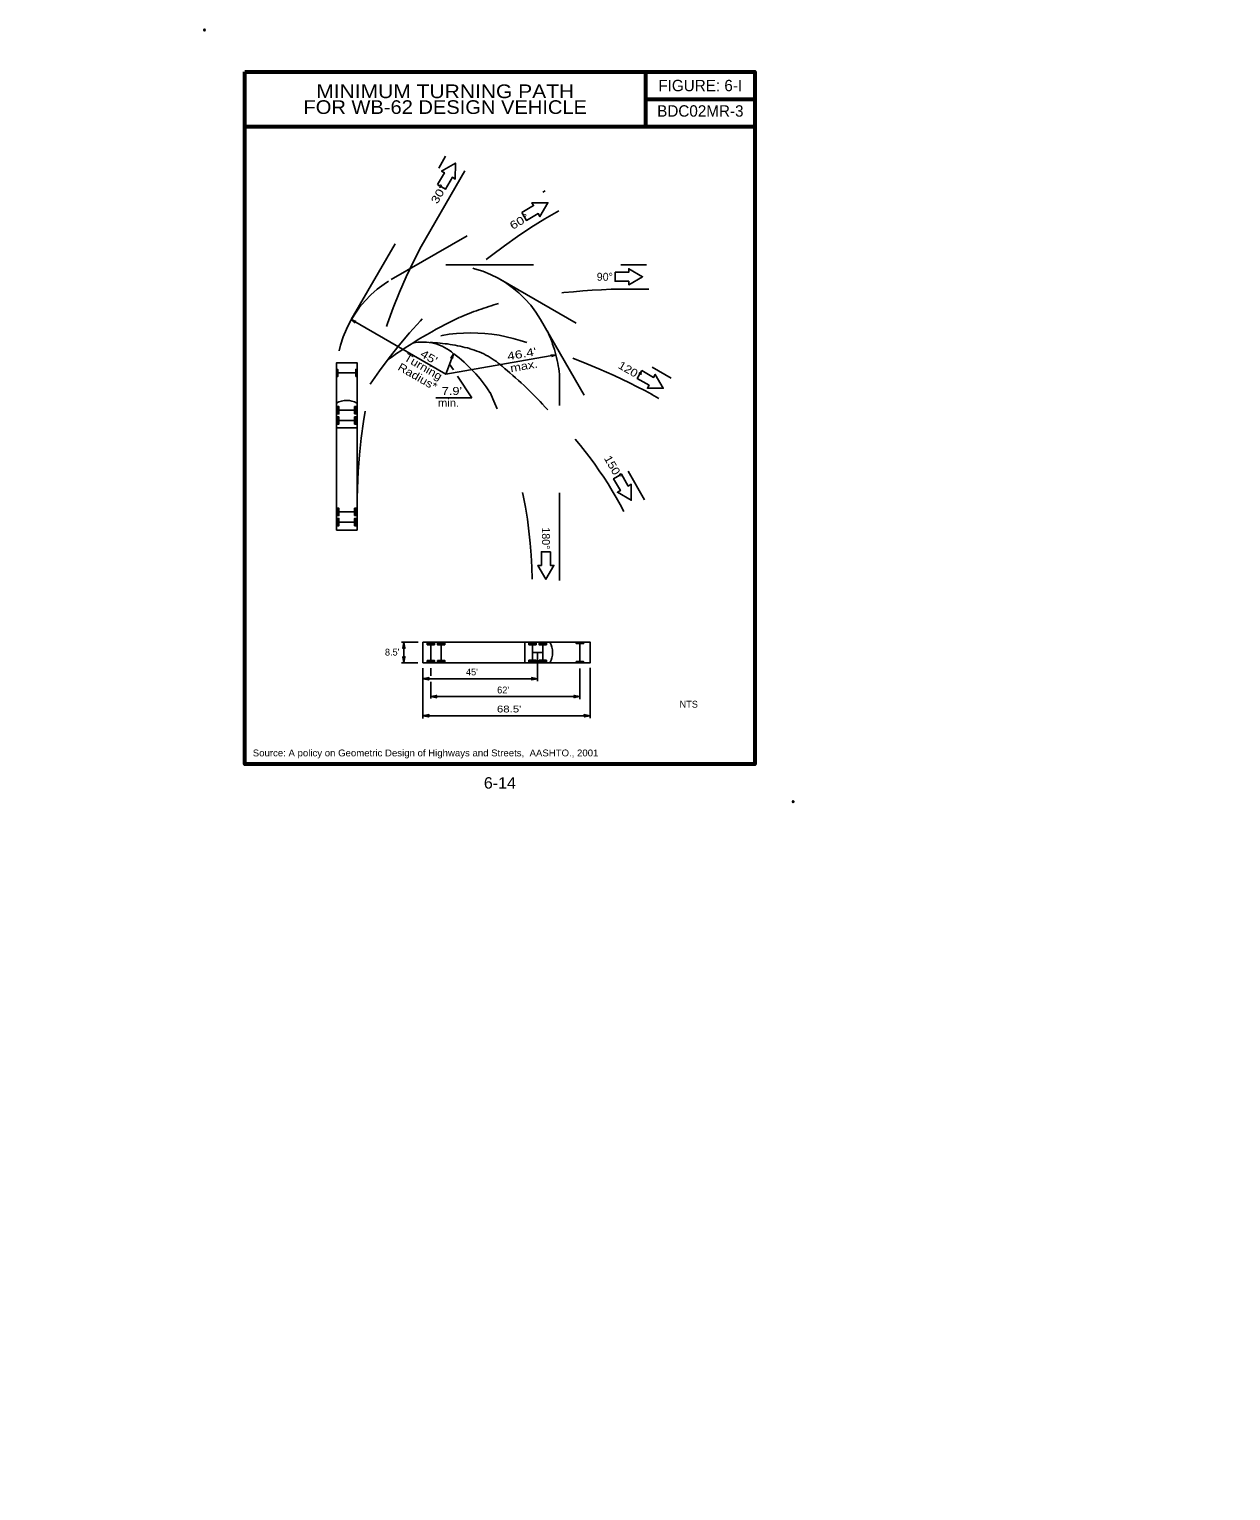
# Model space of a CAD drawing. Extents: x -5.68 to -4.31, y 4.1 to 5.77.
import ezdxf
from ezdxf.enums import TextEntityAlignment as Align

# ---------------------------------------------------------------- set-up
doc = ezdxf.new("R2010")
doc.units = 0
doc.header["$LTSCALE"] = 0.0036
doc.header["$PDMODE"] = 32
doc.header["$PDSIZE"] = 0.0018
doc.linetypes.add('LONG_DASHED', pattern=[7.5, 6, -1.5])
for name, color, linetype, lineweight in [('1', 7, 'Continuous', 25), ('2', 7, 'Continuous', 25), ('24', 7, 'Continuous', 25)]:
    doc.layers.add(name, color=color, linetype=linetype, lineweight=lineweight)

msp = doc.modelspace()

# ---------------------------------------------------------------- linework, layer by layer
at = {"layer": '1', "lineweight": 53}
for p, q in [((-4.977792, 5.724317), (-4.977792, 5.661817)), ((-4.977792, 5.693067), (-4.852792, 5.693067)), ((-5.436125, 5.661817), (-4.852792, 5.661817))]:
    msp.add_line(p, q, dxfattribs=at)
at = {"layer": '1', "linetype": 'LONG_DASHED'}
for p, q in [((-5.314383, 5.441033), (-5.206508, 5.627867)), ((-5.234508, 5.524675), (-5.182825, 5.614192)), ((-5.268633, 5.486783), (-5.092625, 5.5884)), ((-5.206133, 5.503533), (-4.976933, 5.503533)), ((-5.143633, 5.486783), (-4.948617, 5.374175)), ((-5.097883, 5.441033), (-4.978933, 5.235017)), ((-4.97085, 5.355442), (-4.962467, 5.3506))]:
    msp.add_line(p, q, dxfattribs=at)
at = {"layer": '1'}
for p, q in [((-5.314383, 5.441033), (-5.309375, 5.438975)), ((-5.197675, 5.401775), (-5.198808, 5.396483)), ((-5.080467, 5.400692), (-5.08555, 5.398842)), ((-5.329917, 5.37995), (-5.309267, 5.37995)), ((-5.328558, 5.337358), (-5.310708, 5.337358)), ((-5.307892, 5.31705), (-5.331267, 5.31705)), ((-5.328558, 5.325642), (-5.310708, 5.325642)), ((-5.328517, 5.2211), (-5.310667, 5.2211)), ((-5.328517, 5.209383), (-5.310667, 5.209383)), ((-5.237942, 5.071975), (-5.257067, 5.071975)), ((-5.254225, 5.048525), (-5.254225, 5.071933)), ((-5.223442, 5.069183), (-5.223442, 5.051333)), ((-5.211725, 5.069183), (-5.211725, 5.051333)), ((-5.115775, 5.048558), (-5.115775, 5.071933)), ((-5.107183, 5.069225), (-5.107183, 5.051375)), ((-5.095467, 5.069225), (-5.095467, 5.051375)), ((-5.052875, 5.070583), (-5.052875, 5.049933)), ((-5.238183, 5.048533), (-5.257067, 5.048533)), ((-5.107183, 5.0603), (-5.095467, 5.0603)), ((-5.101325, 5.0603), (-5.101325, 5.0432)), ((-5.232558, 5.042483), (-5.232558, 4.984942)), ((-5.223558, 5.042483), (-5.223558, 5.033517)), ((-5.101325, 5.0432), (-5.101325, 5.027375)), ((-5.052875, 5.042), (-5.052875, 5.006983)), ((-5.04115, 5.042608), (-5.04115, 4.985033)), ((-5.2325, 5.030367), (-5.101325, 5.030367)), ((-5.223558, 5.026792), (-5.223558, 5.007583)), ((-5.223558, 5.009867), (-5.052875, 5.009867)), ((-5.23255, 4.988033), (-5.04115, 4.988033))]:
    msp.add_line(p, q, dxfattribs=at)
at = {"layer": '1', "lineweight": 53}
msp.add_lwpolyline([(-5.436125, 5.724317), (-4.852792, 5.724317), (-4.852792, 4.93265), (-5.436125, 4.93265)], close=True, dxfattribs=at)
at = {"layer": '1'}
for points in [[(-5.215633, 5.595392), (-5.206617, 5.590183), (-5.1988, 5.603717), (-5.195425, 5.601758), (-5.195417, 5.619992), (-5.211217, 5.610883), (-5.207825, 5.608925)], [(-5.11935, 5.563508), (-5.114142, 5.554483), (-5.100617, 5.5623), (-5.098667, 5.558908), (-5.089542, 5.5747), (-5.107783, 5.5747), (-5.105825, 5.571317)], [(-5.012617, 5.495192), (-5.012617, 5.484775), (-4.996992, 5.484775), (-4.996992, 5.480867), (-4.9812, 5.489983), (-4.996992, 5.4991), (-4.996992, 5.495192)], [(-5.331308, 5.200267), (-5.331308, 5.391675), (-5.307875, 5.391675), (-5.307875, 5.200267)], [(-5.331308, 5.375783), (-5.331308, 5.384117), (-5.329917, 5.384117), (-5.329917, 5.375783)], [(-5.309267, 5.375783), (-5.309267, 5.384117), (-5.307875, 5.384117), (-5.307875, 5.375783)], [(-4.982158, 5.382725), (-4.987367, 5.3737), (-4.973833, 5.365892), (-4.975792, 5.362517), (-4.95755, 5.362508), (-4.966667, 5.378308), (-4.968625, 5.374908)], [(-5.33135, 5.333192), (-5.33135, 5.341525), (-5.329958, 5.341525), (-5.329958, 5.333192)], [(-5.329958, 5.333192), (-5.329958, 5.341525), (-5.328558, 5.341525), (-5.328558, 5.333192)], [(-5.310708, 5.333192), (-5.310708, 5.341525), (-5.309308, 5.341525), (-5.309308, 5.333192)], [(-5.309308, 5.333192), (-5.309308, 5.341525), (-5.307917, 5.341525), (-5.307917, 5.333192)], [(-5.33135, 5.321475), (-5.33135, 5.329808), (-5.329958, 5.329808), (-5.329958, 5.321475)], [(-5.329958, 5.321475), (-5.329958, 5.329808), (-5.328558, 5.329808), (-5.328558, 5.321475)], [(-5.310708, 5.321475), (-5.310708, 5.329808), (-5.309308, 5.329808), (-5.309308, 5.321475)], [(-5.309308, 5.321475), (-5.309308, 5.329808), (-5.307917, 5.329808), (-5.307917, 5.321475)], [(-5.005467, 5.2642), (-5.014492, 5.258992), (-5.006675, 5.245467), (-5.010058, 5.243517), (-4.994267, 5.234392), (-4.994267, 5.252633), (-4.997658, 5.250675)], [(-5.331308, 5.216933), (-5.331308, 5.225267), (-5.329917, 5.225267), (-5.329917, 5.216933)], [(-5.329917, 5.216933), (-5.329917, 5.225267), (-5.328517, 5.225267), (-5.328517, 5.216933)], [(-5.310667, 5.216933), (-5.310667, 5.225267), (-5.309267, 5.225267), (-5.309267, 5.216933)], [(-5.309267, 5.216933), (-5.309267, 5.225267), (-5.307875, 5.225267), (-5.307875, 5.216933)], [(-5.331308, 5.205217), (-5.331308, 5.21355), (-5.329917, 5.21355), (-5.329917, 5.205217)], [(-5.329917, 5.205217), (-5.329917, 5.21355), (-5.328517, 5.21355), (-5.328517, 5.205217)], [(-5.310667, 5.205217), (-5.310667, 5.21355), (-5.309267, 5.21355), (-5.309267, 5.205217)], [(-5.309267, 5.205217), (-5.309267, 5.21355), (-5.307875, 5.21355), (-5.307875, 5.205217)], [(-5.086575, 5.175575), (-5.096992, 5.175575), (-5.096992, 5.15995), (-5.100892, 5.15995), (-5.091783, 5.144158), (-5.082667, 5.15995), (-5.086575, 5.15995)], [(-5.232558, 5.071975), (-5.04115, 5.071975), (-5.04115, 5.048542), (-5.232558, 5.048542)], [(-5.227608, 5.071975), (-5.219275, 5.071975), (-5.219275, 5.070583), (-5.227608, 5.070583)], [(-5.227608, 5.070583), (-5.219275, 5.070583), (-5.219275, 5.069183), (-5.227608, 5.069183)], [(-5.215892, 5.071975), (-5.207558, 5.071975), (-5.207558, 5.070583), (-5.215892, 5.070583)], [(-5.215892, 5.070583), (-5.207558, 5.070583), (-5.207558, 5.069183), (-5.215892, 5.069183)], [(-5.11135, 5.072017), (-5.103017, 5.072017), (-5.103017, 5.070625), (-5.11135, 5.070625)], [(-5.11135, 5.070625), (-5.103017, 5.070625), (-5.103017, 5.069225), (-5.11135, 5.069225)], [(-5.099633, 5.072017), (-5.0913, 5.072017), (-5.0913, 5.070625), (-5.099633, 5.070625)], [(-5.099633, 5.070625), (-5.0913, 5.070625), (-5.0913, 5.069225), (-5.099633, 5.069225)], [(-5.057042, 5.071975), (-5.048708, 5.071975), (-5.048708, 5.070583), (-5.057042, 5.070583)], [(-5.227608, 5.051333), (-5.219275, 5.051333), (-5.219275, 5.049933), (-5.227608, 5.049933)], [(-5.227608, 5.049933), (-5.219275, 5.049933), (-5.219275, 5.048542), (-5.227608, 5.048542)], [(-5.215892, 5.051333), (-5.207558, 5.051333), (-5.207558, 5.049933), (-5.215892, 5.049933)], [(-5.215892, 5.049933), (-5.207558, 5.049933), (-5.207558, 5.048542), (-5.215892, 5.048542)], [(-5.11135, 5.051375), (-5.103017, 5.051375), (-5.103017, 5.049975), (-5.11135, 5.049975)], [(-5.11135, 5.049975), (-5.103017, 5.049975), (-5.103017, 5.048583), (-5.11135, 5.048583)], [(-5.099633, 5.051375), (-5.0913, 5.051375), (-5.0913, 5.049975), (-5.099633, 5.049975)], [(-5.099633, 5.049975), (-5.0913, 5.049975), (-5.0913, 5.048583), (-5.099633, 5.048583)], [(-5.057042, 5.049933), (-5.048708, 5.049933), (-5.048708, 5.048542), (-5.057042, 5.048542)]]:
    msp.add_lwpolyline(points, close=True, dxfattribs=at)
for points in [[(-5.310558, 5.438767), (-5.3101, 5.437492), (-5.314433, 5.441075)], [(-5.309383, 5.43895), (-5.31055, 5.438783), (-5.310558, 5.438767)], [(-5.199225, 5.397608), (-5.200392, 5.396933), (-5.197642, 5.401825)], [(-5.084825, 5.399775), (-5.086008, 5.400408), (-5.080408, 5.400692)], [(-5.085558, 5.39885), (-5.084808, 5.399758), (-5.084825, 5.399775)], [(-5.198833, 5.396483), (-5.199208, 5.3976), (-5.199225, 5.397608)]]:
    msp.add_lwpolyline(points, dxfattribs=at)
at = {"layer": '1', "linetype": 'LONG_DASHED'}
for centre, radius, start, end in [((-4.762043, 5.006607), 0.641577, 119.41729, 145.80266), ((-4.680067, 5.2306), 0.6276, 152.05893, 180.18091), ((-5.206134, 5.378533), 0.124999, 30.00165, 173.73609), ((-4.995637, 4.78883), 0.687172, 104.54706, 104.54706), ((-4.995637, 4.78883), 0.687172, 88.19199, 102.632), ((-5.02827, 5.055001), 0.42117, 106.21202, 112.69666), ((-4.940301, 4.927228), 0.573947, 115.91033, 125.34278), ((-5.177753, 5.2346), 0.191176, 70.39355, 109.69824), ((-5.240169, 5.359419), 0.16495, 6.65496, 24.52545), ((-5.232969, 5.361338), 0.054029, 48.88452, 101.79293), ((-5.23051, 5.225607), 0.189329, 74.18371, 88.12314), ((-5.301691, 5.263026), 0.173897, 32.98189, 53.0645), ((-5.204774, 5.315343), 0.09593, 47.34966, 74.27114), ((-5.328395, 4.69157), 0.754139, 61.6475, 73.45199), ((-5.41536, 5.047903), 0.43596, 41.67879, 50.76022), ((-5.643182, 5.135495), 0.535722, 0.92351, 24.49207), ((-5.420256, 4.999834), 0.472969, 27.97988, 45.5368)]:
    msp.add_arc(centre, radius, start, end, dxfattribs=at)
at = {"layer": '1'}
for centre, start, end in [((-5.319665, 5.325201), 60.0609, 119.9391), ((-5.107624, 5.060331), 330.0609, 29.9391)]:
    msp.add_arc(centre, 0.023418, start, end, dxfattribs=at)
for p in [(-5.482375, 5.772175), (-4.809042, 4.889675)]:
    msp.add_point(p, dxfattribs=at)
at = {"layer": '2'}
for p, q in [((-5.206133, 5.378533), (-5.314383, 5.441033)), ((-5.206133, 5.378533), (-5.197675, 5.401783)), ((-5.206133, 5.378533), (-5.080467, 5.400692)), ((-5.197442, 5.383375), (-5.201908, 5.390158)), ((-5.176483, 5.351583), (-5.192908, 5.376492)), ((-5.217567, 5.351583), (-5.176483, 5.351583))]:
    msp.add_line(p, q, dxfattribs=at)
at = {"layer": '2', "linetype": 'LONG_DASHED'}
msp.add_line((-5.076333, 5.142817), (-5.076333, 5.378533), dxfattribs=at)
at = {"layer": '24'}
for points in [[(-5.254225, 5.071933), (-5.25545, 5.065), (-5.254225, 5.066658), (-5.253017, 5.065042), (-5.254225, 5.071933), (-5.254217, 5.071475), (-5.255358, 5.0652), (-5.254208, 5.066792), (-5.253117, 5.065317), (-5.254192, 5.071225), (-5.254225, 5.070992), (-5.255183, 5.065617), (-5.254208, 5.066825), (-5.253267, 5.065583), (-5.254225, 5.070892), (-5.254192, 5.070658), (-5.255042, 5.065958), (-5.254225, 5.066875), (-5.253383, 5.065942), (-5.254192, 5.069992), (-5.254192, 5.0696), (-5.254867, 5.066308), (-5.254242, 5.06695), (-5.253558, 5.066258), (-5.254225, 5.069525), (-5.25425, 5.069158), (-5.254667, 5.066683), (-5.254192, 5.067158), (-5.253717, 5.066642), (-5.254225, 5.068817), (-5.254258, 5.068467), (-5.254542, 5.066983), (-5.254208, 5.067225), (-5.253842, 5.066825), (-5.254225, 5.068292), (-5.254458, 5.067317), (-5.254192, 5.067458), (-5.253925, 5.067033), (-5.254192, 5.068042), (-5.25435, 5.067408), (-5.254142, 5.067675), (-5.254017, 5.067367), (-5.254208, 5.067675), (-5.254242, 5.067517)], [(-5.254225, 5.048525), (-5.253, 5.055458), (-5.254225, 5.0538), (-5.255433, 5.055417), (-5.254225, 5.048525), (-5.254242, 5.048983), (-5.253092, 5.055258), (-5.254242, 5.053667), (-5.255333, 5.055142), (-5.254258, 5.049233), (-5.254225, 5.049467), (-5.253267, 5.054842), (-5.254242, 5.053633), (-5.255183, 5.054875), (-5.254225, 5.049567), (-5.254258, 5.0498), (-5.253408, 5.0545), (-5.254225, 5.053583), (-5.255067, 5.054517), (-5.254258, 5.050467), (-5.254258, 5.050858), (-5.253583, 5.05415), (-5.254208, 5.053508), (-5.254892, 5.0542), (-5.254225, 5.050933), (-5.2542, 5.0513), (-5.253783, 5.053775), (-5.254258, 5.0533), (-5.254733, 5.053817), (-5.254225, 5.051642), (-5.254192, 5.051992), (-5.253908, 5.053475), (-5.254242, 5.053233), (-5.254608, 5.053633), (-5.254225, 5.052167), (-5.253992, 5.053142), (-5.254258, 5.053), (-5.254525, 5.053425), (-5.254258, 5.052417), (-5.2541, 5.05305), (-5.254308, 5.052783), (-5.254433, 5.053092), (-5.254242, 5.052783), (-5.254208, 5.052942)], [(-5.2325, 5.030367), (-5.225567, 5.029142), (-5.227225, 5.030367), (-5.225608, 5.031575), (-5.2325, 5.030367), (-5.232042, 5.030383), (-5.225767, 5.029233), (-5.227358, 5.030383), (-5.225883, 5.031475), (-5.231792, 5.0304), (-5.231558, 5.030367), (-5.226183, 5.029408), (-5.227392, 5.030383), (-5.22615, 5.031325), (-5.231458, 5.030367), (-5.231225, 5.0304), (-5.226525, 5.02955), (-5.227442, 5.030367), (-5.226508, 5.031208), (-5.230558, 5.0304), (-5.230167, 5.0304), (-5.226875, 5.029725), (-5.227517, 5.03035), (-5.226825, 5.031033), (-5.230092, 5.030367), (-5.229725, 5.030342), (-5.22725, 5.029925), (-5.227725, 5.0304), (-5.227208, 5.030875), (-5.229383, 5.030367), (-5.229033, 5.030333), (-5.22755, 5.03005), (-5.227792, 5.030383), (-5.227392, 5.03075), (-5.228858, 5.030367), (-5.227883, 5.030133), (-5.228025, 5.0304), (-5.2276, 5.030667), (-5.228608, 5.0304), (-5.227975, 5.030242), (-5.228242, 5.03045), (-5.227933, 5.030575), (-5.228242, 5.030383), (-5.228083, 5.03035)], [(-5.101325, 5.030367), (-5.108258, 5.031592), (-5.1066, 5.030367), (-5.108217, 5.029158), (-5.101325, 5.030367), (-5.101783, 5.030358), (-5.108058, 5.0315), (-5.106467, 5.03035), (-5.107942, 5.029258), (-5.102033, 5.030333), (-5.102267, 5.030367), (-5.107642, 5.031325), (-5.106433, 5.03035), (-5.107675, 5.029408), (-5.102367, 5.030367), (-5.1026, 5.030333), (-5.1073, 5.031183), (-5.106383, 5.030367), (-5.107317, 5.029525), (-5.103267, 5.030333), (-5.103658, 5.030333), (-5.10695, 5.031008), (-5.106308, 5.030383), (-5.107, 5.0297), (-5.103733, 5.030367), (-5.1041, 5.030392), (-5.106575, 5.030808), (-5.1061, 5.030333), (-5.106617, 5.029858), (-5.104442, 5.030367), (-5.104792, 5.0304), (-5.106275, 5.030683), (-5.106033, 5.03035), (-5.106433, 5.029983), (-5.104967, 5.030367), (-5.105942, 5.0306), (-5.1058, 5.030333), (-5.106225, 5.030067), (-5.105217, 5.030333), (-5.10585, 5.030492), (-5.105583, 5.030283), (-5.105892, 5.030158), (-5.105583, 5.03035), (-5.105742, 5.030383)], [(-5.223558, 5.009867), (-5.216625, 5.008642), (-5.218283, 5.009867), (-5.216667, 5.011075), (-5.223558, 5.009867), (-5.2231, 5.009883), (-5.216825, 5.008733), (-5.218417, 5.009883), (-5.216942, 5.010975), (-5.22285, 5.0099), (-5.222617, 5.009867), (-5.217242, 5.008908), (-5.21845, 5.009883), (-5.217208, 5.010825), (-5.222517, 5.009867), (-5.222283, 5.0099), (-5.217583, 5.00905), (-5.2185, 5.009867), (-5.217567, 5.010708), (-5.221617, 5.0099), (-5.221225, 5.0099), (-5.217933, 5.009225), (-5.218575, 5.00985), (-5.217883, 5.010533), (-5.22115, 5.009867), (-5.220783, 5.009842), (-5.218308, 5.009425), (-5.218783, 5.0099), (-5.218267, 5.010375), (-5.220442, 5.009867), (-5.220092, 5.009833), (-5.218608, 5.00955), (-5.21885, 5.009883), (-5.21845, 5.01025), (-5.219917, 5.009867), (-5.218942, 5.009633), (-5.219083, 5.0099), (-5.218658, 5.010167), (-5.219667, 5.0099), (-5.219033, 5.009742), (-5.2193, 5.00995), (-5.218992, 5.010075), (-5.2193, 5.009883), (-5.219142, 5.00985)], [(-5.052875, 5.009867), (-5.059808, 5.011092), (-5.05815, 5.009867), (-5.059767, 5.008658), (-5.052875, 5.009867), (-5.053333, 5.009858), (-5.059608, 5.011), (-5.058017, 5.00985), (-5.059492, 5.008758), (-5.053583, 5.009833), (-5.053817, 5.009867), (-5.059192, 5.010825), (-5.057983, 5.00985), (-5.059225, 5.008908), (-5.053917, 5.009867), (-5.05415, 5.009833), (-5.05885, 5.010683), (-5.057933, 5.009867), (-5.058867, 5.009025), (-5.054817, 5.009833), (-5.055208, 5.009833), (-5.0585, 5.010508), (-5.057858, 5.009883), (-5.05855, 5.0092), (-5.055283, 5.009867), (-5.05565, 5.009892), (-5.058125, 5.010308), (-5.05765, 5.009833), (-5.058167, 5.009358), (-5.055992, 5.009867), (-5.056342, 5.0099), (-5.057825, 5.010183), (-5.057583, 5.00985), (-5.057983, 5.009483), (-5.056517, 5.009867), (-5.057492, 5.0101), (-5.05735, 5.009833), (-5.057775, 5.009567), (-5.056767, 5.009833), (-5.0574, 5.009992), (-5.057133, 5.009783), (-5.057442, 5.009658), (-5.057133, 5.00985), (-5.057292, 5.009883)], [(-5.23255, 4.988033), (-5.225617, 4.986808), (-5.227275, 4.988033), (-5.225658, 4.989242), (-5.23255, 4.988033), (-5.232092, 4.98805), (-5.225817, 4.9869), (-5.227408, 4.98805), (-5.225933, 4.989142), (-5.231842, 4.988067), (-5.231608, 4.988033), (-5.226233, 4.987075), (-5.227442, 4.98805), (-5.2262, 4.988992), (-5.231508, 4.988033), (-5.231275, 4.988067), (-5.226575, 4.987217), (-5.227492, 4.988033), (-5.226558, 4.988875), (-5.230608, 4.988067), (-5.230217, 4.988067), (-5.226925, 4.987392), (-5.227567, 4.988017), (-5.226875, 4.9887), (-5.230142, 4.988033), (-5.229775, 4.988008), (-5.2273, 4.987592), (-5.227775, 4.988067), (-5.227258, 4.988542), (-5.229433, 4.988033), (-5.229083, 4.988), (-5.2276, 4.987717), (-5.227842, 4.98805), (-5.227442, 4.988417), (-5.228908, 4.988033), (-5.227933, 4.9878), (-5.228075, 4.988067), (-5.22765, 4.988333), (-5.228658, 4.988067), (-5.228025, 4.987908), (-5.228292, 4.988117), (-5.227983, 4.988242), (-5.228292, 4.98805), (-5.228133, 4.988017)], [(-5.04115, 4.988033), (-5.048083, 4.989258), (-5.046425, 4.988033), (-5.048042, 4.986825), (-5.04115, 4.988033), (-5.041608, 4.988025), (-5.047883, 4.989167), (-5.046292, 4.988017), (-5.047767, 4.986925), (-5.041858, 4.988), (-5.042092, 4.988033), (-5.047467, 4.988992), (-5.046258, 4.988017), (-5.0475, 4.987075), (-5.042192, 4.988033), (-5.042425, 4.988), (-5.047125, 4.98885), (-5.046208, 4.988033), (-5.047142, 4.987192), (-5.043092, 4.988), (-5.043483, 4.988), (-5.046775, 4.988675), (-5.046133, 4.98805), (-5.046825, 4.987367), (-5.043558, 4.988033), (-5.043925, 4.988058), (-5.0464, 4.988475), (-5.045925, 4.988), (-5.046442, 4.987525), (-5.044267, 4.988033), (-5.044617, 4.988067), (-5.0461, 4.98835), (-5.045858, 4.988017), (-5.046258, 4.98765), (-5.044792, 4.988033), (-5.045767, 4.988267), (-5.045625, 4.988), (-5.04605, 4.987733), (-5.045042, 4.988), (-5.045675, 4.988158), (-5.045408, 4.98795), (-5.045717, 4.987825), (-5.045408, 4.988017), (-5.045567, 4.98805)]]:
    msp.add_lwpolyline(points, dxfattribs=at)

# ---------------------------------------------------------------- texts
at = {"layer": '1'}
for s, height, width, p in [('MINIMUM TURNING PATH', 0.01562, 1.15, (-5.206958, 5.694292)), ('FOR WB-62 DESIGN VEHICLE', 0.01562, 1.1, (-5.206958, 5.676217)), ('min.', 0.009117, 1.05, (-5.203229, 5.341258)), ("7.9'", 0.009117, 1.2, (-5.199454, 5.354817)), ('6-14', 0.01303, 1.05, (-5.144463, 4.90465))]:
    msp.add_text(s, height=height, dxfattribs=dict(at, width=width)).set_placement(p, align=Align.CENTER)
for s, height, p in [('FIGURE: 6-I', 0.01303, (-4.915292, 5.702175)), ('BDC02MR-3', 0.01303, (-4.915171, 5.6731)), ('NTS', 0.007817, (-4.928454, 4.997225))]:
    msp.add_text(s, height=height, dxfattribs=at).set_placement(p, align=Align.CENTER)
for s, rotation, width, p in [('30°', 60, 1.25, (-5.204546, 5.592462)), ('60°', 30, 1.25, (-5.109921, 5.555074)), ('120°', 330, 1.15, (-4.985096, 5.371639)), ('150°', 300, 1.15, (-5.011306, 5.257371))]:
    msp.add_text(s, height=0.009108, rotation=rotation, dxfattribs=dict(at, width=width)).set_placement(p, align=Align.RIGHT)
msp.add_text('90°', height=0.009108, dxfattribs=at).set_placement((-5.015225, 5.485425), align=Align.RIGHT)
for s, rotation, width, p in [('Turning', 329.999, 1.15, (-5.234321, 5.383065)), ("45'", 329.999, 1.25, (-5.227817, 5.394346)), ("46.4'", 9.999, 1.3, (-5.118629, 5.397299)), ('Radius*', 329.999, 1.15, (-5.240833, 5.371788)), ('max.', 9.999, 1.2, (-5.116191, 5.383497))]:
    msp.add_text(s, height=0.009117, rotation=rotation, dxfattribs=dict(at, width=width)).set_placement(p, align=Align.CENTER)
msp.add_text('180°', height=0.009108, rotation=270, dxfattribs=at).set_placement((-5.096342, 5.178183), align=Align.RIGHT)
for s, p in [("8.5'", (-5.275958, 5.056808)), ("45'", (-5.183258, 5.034125)), ("62'", (-5.14755, 5.013525))]:
    msp.add_text(s, height=0.007817, dxfattribs=at).set_placement(p)
for s, width, p in [("68.5'", 1.25, (-5.147858, 4.99175)), ('Source: A policy on Geometric Design of Highways and Streets,  AASHTO., 2001', 1.05, (-5.427125, 4.941517))]:
    msp.add_text(s, height=0.007817, dxfattribs=dict(at, width=width)).set_placement(p)

doc.saveas('drawing.dxf')
